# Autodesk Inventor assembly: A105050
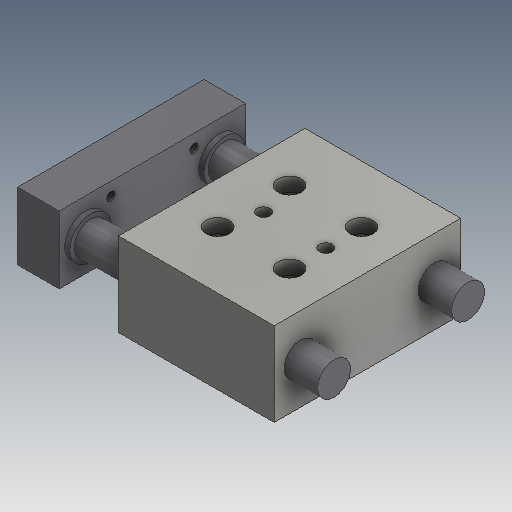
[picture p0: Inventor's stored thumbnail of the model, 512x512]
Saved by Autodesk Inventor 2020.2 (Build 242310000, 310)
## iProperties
Created: 2000-01
Part Number: A105050
Document SubType Name: Assembly
Designer: tgregory
Mass: 372.4 g
Surface Area: 247.241 cm^2
Volume: 86.5264 cm^3
Density: 4.30389 g/cm^3
Control State: 0
Master: False
Checked Out: False
Shininess: 0.0
Length Units: 11269
Angle Units: 11279
Time Units: 11290
Mass Units: 11283
Length Display Precision: 3
Angle Display Precision: 2
Compacted: True
Dimensions: 25,6x57x88,8 mm
Mass: 0,372 kg
DocNumber: A105050.iam
Folder: 01 - Themengebiete\Simplification\01 - Packaging machine\
VDS_Category: 3D Komponenten
Density: 0.0
Volumn: 0.0
Area: 0.0
PropertySet Name: Model Information
Author: tgregory
Revision Number: -
Title: Zylinder
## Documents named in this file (3)
- D:\07 - DEMODATEN\OTX 2019 - Dataset - UPDATE - Dez2019\Designs\07-Packing machine\A105050.iam
- D:\07 - DEMODATEN\OTX 2019 - Dataset - UPDATE - Dez2019\Designs\07-Packing machine\Parts\ADSK-011846.ipt
- D:\07 - DEMODATEN\OTX 2019 - Dataset - UPDATE - Dez2019\Designs\07-Packing machine\Parts\ADSK-011845.ipt
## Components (2 placed, 2 different names)
1. SA-033X0.5-BODY.ipt:1 — Mate:1, Mate:2, stroke
2. ADSK-011846:1 — Mate:1, Mate:2, stroke
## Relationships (3: Mate 3)
- Mate:1: SA-033X0.5-BODY.ipt:1 ↔ ADSK-011846:1
- Mate:2: SA-033X0.5-BODY.ipt:1 ↔ ADSK-011846:1
- stroke [Mate]: SA-033X0.5-BODY.ipt:1 ↔ ADSK-011846:1
